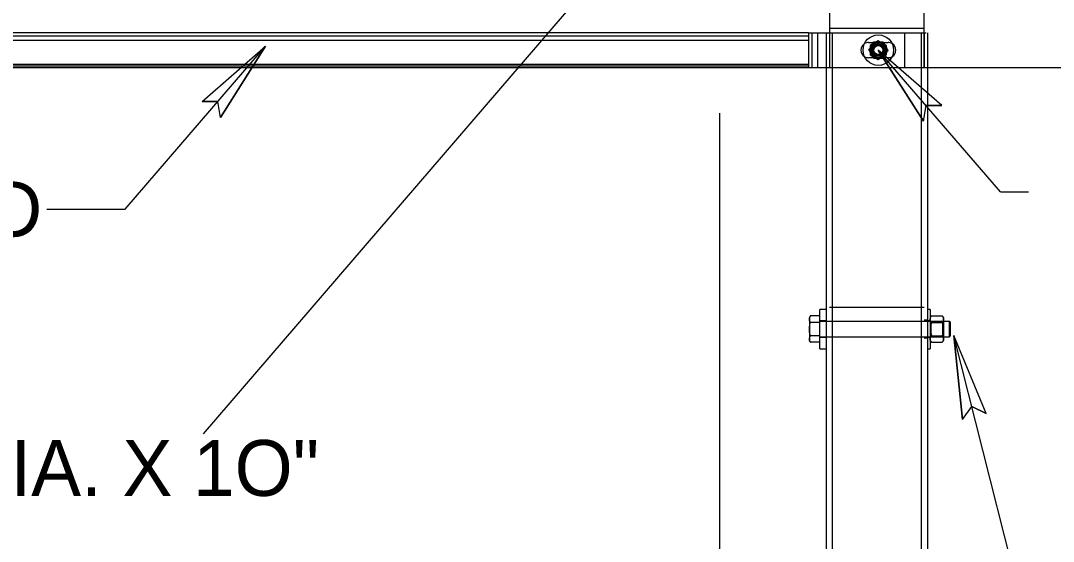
# Model space of a CAD drawing. Extents: x 12.2 to 54.5, y -7.8 to 16.1.
# Drawn here: x 14.18 to 15.289, y 14.128 to 14.687 of the extents above; entities that cross this region are included whole.
import ezdxf

# ---------------------------------------------------------------- set-up
doc = ezdxf.new("R2010")
doc.units = 0
for name, color, linetype in [('BORD-LINE', 7, 'Continuous'), ('DETL-DIMS', 7, 'Continuous'), ('DETL-NOTE', 7, 'Continuous')]:
    doc.layers.add(name, color=color, linetype=linetype)

msp = doc.modelspace()

# ---------------------------------------------------------------- linework, layer by layer
at = {"layer": 'BORD-LINE'}
for p, q in [((15.0489, 15.2577), (15.0489, 14.6363)), ((15.1503, 15.2577), (15.1503, 14.6362)), ((15.0264, 14.6743), (13.7714, 14.6743)), ((15.0264, 14.6706), (13.7714, 14.6706)), ((15.0264, 14.6743), (15.0264, 14.6369)), ((15.0264, 14.6743), (15.0358, 14.6743)), ((15.0299, 14.6743), (15.0299, 14.6369)), ((15.0358, 14.6743), (15.0358, 14.6369)), ((15.0358, 14.6743), (15.1294, 14.6743)), ((15.0451, 14.6743), (15.0451, 13.3257)), ((15.0517, 14.6743), (15.0517, 13.3257)), ((15.1294, 14.6743), (15.1294, 14.6369)), ((15.1294, 14.6743), (15.1528, 14.6743)), ((15.1474, 14.6743), (15.1474, 13.3257)), ((15.1505, 14.6743), (15.1505, 14.6369)), ((15.154, 14.6743), (15.154, 13.3257)), ((15.0264, 14.6659), (13.7714, 14.6659)), ((15.0908, 14.6638), (15.1119, 14.6638)), ((15.1013, 14.6657), (15.0926, 14.6606)), ((15.0926, 14.6606), (15.0926, 14.6506)), ((15.11, 14.6606), (15.1013, 14.6657)), ((15.11, 14.6506), (15.11, 14.6606)), ((15.1119, 14.6474), (15.0908, 14.6474)), ((15.0926, 14.6506), (15.1013, 14.6456)), ((15.1013, 14.6456), (15.11, 14.6506)), ((12.3965, 14.6369), (18.9405, 14.6369)), ((15.0264, 14.6403), (13.7714, 14.6403)), ((15.0264, 14.6384), (13.7714, 14.6384)), ((15.0487, 14.3794), (15.1507, 14.3794)), ((15.0272, 14.3682), (15.0272, 14.3666)), ((15.0386, 14.3701), (15.0283, 14.3701)), ((15.0386, 14.3348), (15.0386, 14.377)), ((15.1569, 14.377), (15.1569, 14.3348)), ((15.1586, 14.3701), (15.1698, 14.3701)), ((15.1715, 14.3682), (15.1715, 14.3666)), ((15.0272, 14.3666), (15.0272, 14.3559)), ((15.0386, 14.363), (15.0283, 14.363)), ((15.157, 14.3641), (15.157, 14.3559)), ((15.1577, 14.3631), (15.1577, 14.3487)), ((15.1586, 14.363), (15.1698, 14.363)), ((15.1707, 14.3559), (15.1707, 14.3631)), ((15.1715, 14.3666), (15.1715, 14.3559)), ((15.1778, 14.3477), (15.1778, 14.3641)), ((15.179, 14.349), (15.179, 14.3629)), ((15.0272, 14.3559), (15.0272, 14.3453)), ((15.0272, 14.3453), (15.0272, 14.3436)), ((15.0386, 14.3488), (15.0283, 14.3488)), ((15.157, 14.3559), (15.157, 14.3477)), ((15.1586, 14.3488), (15.1698, 14.3488)), ((15.1707, 14.3487), (15.1707, 14.3559)), ((15.1715, 14.3559), (15.1715, 14.3453)), ((15.1715, 14.3453), (15.1715, 14.3436)), ((15.0386, 14.3417), (15.0283, 14.3417)), ((15.1586, 14.3417), (15.1698, 14.3417))]:
    msp.add_line(p, q, dxfattribs=at)
for radius in [0.0164, 0.00819, 0.00702, 0.00614, 0.00585, 0.00498, 0.00484]:
    msp.add_circle((15.1013, 14.6556), radius, dxfattribs=at)
for centre, radius, start, end in [((15.0908, 14.6556), 0.00819, 121.5884, 238.4116), ((15.0908, 14.6556), 0.00819, 89.9961, 121.5935), ((15.1013, 14.6556), 0.00869, 119.9904, 180.0097), ((15.1013, 14.6556), 0.00878, 149.9916, 210.0084), ((15.1013, 14.6556), 0.00878, 89.9977, 150.0011), ((15.1013, 14.6556), 0.00869, 59.9984, 120.0016), ((15.1013, 14.6556), 0.00878, 29.9989, 89.9977), ((15.1013, 14.6556), 0.00869, 0.0053, 59.9946), ((15.1013, 14.6556), 0.00878, 329.9916, 30.0084), ((15.1119, 14.6556), 0.0082, 58.4163, 89.999), ((15.1119, 14.6556), 0.00819, 301.5884, 58.4116), ((15.0908, 14.6556), 0.00819, 238.409, 270.0014), ((15.1013, 14.6556), 0.00869, 179.9903, 240.0096), ((15.1013, 14.6556), 0.00878, 209.9989, 270.0023), ((15.1013, 14.6556), 0.00869, 239.9984, 300.0016), ((15.1013, 14.6556), 0.00878, 270.0023, 330.0011), ((15.1013, 14.6556), 0.00869, 300.0054, 359.9947), ((15.1119, 14.6556), 0.0082, 270.0057, 301.579)]:
    msp.add_arc(centre, radius, start, end, dxfattribs=at)
for points, degree in [([(15.0487, 14.679), (15.1504, 14.679)], 1), ([(15.0912, 14.6556), (15.0916, 14.6563), (15.0924, 14.6578), (15.0933, 14.6592), (15.0937, 14.66), (15.0937, 14.66)], 3), ([(15.0937, 14.66), (15.0941, 14.6606), (15.0948, 14.6618), (15.0956, 14.6633), (15.0961, 14.6642), (15.0963, 14.6644)], 3), ([(15.0963, 14.6644), (15.0967, 14.6644), (15.0977, 14.6644), (15.0994, 14.6644), (15.1007, 14.6644), (15.1013, 14.6644)], 3), ([(15.1013, 14.6644), (15.1015, 14.6644), (15.1022, 14.6644), (15.1036, 14.6644), (15.1052, 14.6644), (15.1061, 14.6644), (15.1064, 14.6644)], 3), ([(15.1064, 14.6644), (15.1068, 14.6637), (15.1076, 14.6623), (15.1085, 14.6608), (15.1089, 14.66), (15.1089, 14.66)], 3), ([(15.1089, 14.66), (15.1093, 14.6594), (15.11, 14.6582), (15.1109, 14.6567), (15.1113, 14.6559), (15.1115, 14.6556)], 3), ([(15.0937, 14.6512), (15.0934, 14.6518), (15.0927, 14.6531), (15.0918, 14.6545), (15.0913, 14.6554), (15.0912, 14.6556)], 3), ([(15.0963, 14.6468), (15.0959, 14.6475), (15.095, 14.649), (15.0942, 14.6504), (15.0937, 14.6512), (15.0937, 14.6512)], 3), ([(15.0963, 14.6468), (15.0967, 14.6468), (15.0977, 14.6468), (15.0994, 14.6468), (15.1007, 14.6468), (15.1013, 14.6468)], 3), ([(15.1013, 14.6468), (15.1015, 14.6468), (15.1022, 14.6468), (15.1036, 14.6468), (15.1052, 14.6468), (15.1061, 14.6468), (15.1064, 14.6468)], 3), ([(15.1089, 14.6512), (15.1086, 14.6506), (15.1079, 14.6494), (15.107, 14.6479), (15.1065, 14.6471), (15.1064, 14.6468)], 3), ([(15.1115, 14.6556), (15.1111, 14.6549), (15.1102, 14.6535), (15.1094, 14.652), (15.109, 14.6512), (15.1089, 14.6512)], 3), ([(15.0272, 14.3666), (15.0272, 14.3666), (15.0272, 14.3673), (15.0275, 14.3685), (15.0281, 14.3696), (15.0283, 14.3701)], 3), ([(15.0283, 14.3701), (15.0272, 14.3682)], 1), ([(15.045, 14.377), (15.0386, 14.377)], 1), ([(15.1569, 14.377), (15.1539, 14.377)], 1), ([(15.1569, 14.3666), (15.157, 14.3671), (15.1571, 14.3681), (15.1579, 14.3693), (15.1584, 14.3699), (15.1586, 14.3701)], 3), ([(15.1586, 14.3701), (15.1569, 14.3682)], 1), ([(15.1715, 14.3666), (15.1714, 14.3671), (15.1713, 14.3681), (15.1705, 14.3693), (15.17, 14.3699), (15.1698, 14.3701)], 3), ([(15.1715, 14.3682), (15.1698, 14.3701)], 1), ([(15.0283, 14.363), (15.028, 14.3636), (15.0274, 14.3647), (15.0273, 14.3659), (15.0272, 14.3666)], 3), ([(15.0272, 14.3559), (15.0273, 14.3569), (15.0273, 14.3587), (15.0278, 14.3611), (15.0282, 14.3625), (15.0283, 14.363)], 3), ([(15.0451, 14.3647), (15.0386, 14.3647)], 1), ([(15.1778, 14.3641), (15.0386, 14.3641)], 1), ([(15.1539, 14.3653), (15.1504, 14.3653)], 1), ([(15.1569, 14.3647), (15.1539, 14.3647)], 1), ([(15.1586, 14.363), (15.1581, 14.3635), (15.1573, 14.3646), (15.1569, 14.3659), (15.1569, 14.3665), (15.1569, 14.3666)], 3), ([(15.157, 14.3641), (15.1569, 14.3641)], 1), ([(15.1586, 14.363), (15.1583, 14.3624), (15.1578, 14.361), (15.1571, 14.3586), (15.157, 14.3568), (15.1569, 14.3559)], 3), ([(15.1577, 14.3631), (15.157, 14.3641)], 1), ([(15.1707, 14.3631), (15.1577, 14.3631)], 1), ([(15.1698, 14.363), (15.1703, 14.3635), (15.1711, 14.3646), (15.1715, 14.3659), (15.1715, 14.3665), (15.1715, 14.3666)], 3), ([(15.1698, 14.363), (15.1701, 14.3624), (15.1706, 14.361), (15.1713, 14.3586), (15.1714, 14.3568), (15.1715, 14.3559)], 3), ([(15.1715, 14.3641), (15.1707, 14.3631)], 1), ([(15.179, 14.3629), (15.1778, 14.3641)], 1), ([(15.0283, 14.3488), (15.0281, 14.3497), (15.0276, 14.3515), (15.0273, 14.3539), (15.0273, 14.3554), (15.0272, 14.3559)], 3), ([(15.0272, 14.3453), (15.0272, 14.3454), (15.0272, 14.346), (15.0275, 14.3473), (15.0281, 14.3483), (15.0283, 14.3488)], 3), ([(15.0283, 14.3417), (15.028, 14.3423), (15.0274, 14.3434), (15.0273, 14.3447), (15.0272, 14.3453)], 3), ([(15.0386, 14.3477), (15.1778, 14.3477)], 1), ([(15.0386, 14.3471), (15.045, 14.3471)], 1), ([(15.1504, 14.3466), (15.1539, 14.3466)], 1), ([(15.1539, 14.3471), (15.1569, 14.3471)], 1), ([(15.1569, 14.3559), (15.1569, 14.3558), (15.1569, 14.3547), (15.1572, 14.3527), (15.1579, 14.3505), (15.1584, 14.3492), (15.1586, 14.3488)], 3), ([(15.1569, 14.3453), (15.157, 14.3458), (15.1571, 14.3469), (15.1579, 14.348), (15.1584, 14.3486), (15.1586, 14.3488)], 3), ([(15.1569, 14.3477), (15.157, 14.3477)], 1), ([(15.1586, 14.3417), (15.1581, 14.3423), (15.1573, 14.3433), (15.1569, 14.3446), (15.1569, 14.3453), (15.1569, 14.3453)], 3), ([(15.1569, 14.3453), (15.157, 14.3451)], 1), ([(15.157, 14.3477), (15.1577, 14.3487)], 1), ([(15.1577, 14.3487), (15.1707, 14.3487)], 1), ([(15.1715, 14.3559), (15.1715, 14.3558), (15.1715, 14.3547), (15.1712, 14.3527), (15.1705, 14.3505), (15.17, 14.3492), (15.1698, 14.3488)], 3), ([(15.1715, 14.3453), (15.1714, 14.3458), (15.1713, 14.3469), (15.1705, 14.348), (15.17, 14.3486), (15.1698, 14.3488)], 3), ([(15.1698, 14.3417), (15.1703, 14.3423), (15.1711, 14.3433), (15.1715, 14.3446), (15.1715, 14.3453), (15.1715, 14.3453)], 3), ([(15.1707, 14.3487), (15.1715, 14.3477)], 1), ([(15.1778, 14.3477), (15.179, 14.349)], 1), ([(15.0272, 14.3436), (15.0283, 14.3417)], 1), ([(15.0386, 14.3348), (15.045, 14.3348)], 1), ([(15.1539, 14.3348), (15.1569, 14.3348)], 1), ([(15.1569, 14.3436), (15.1586, 14.3417)], 1), ([(15.1698, 14.3417), (15.1715, 14.3436)], 1)]:
    msp.add_open_spline(points, degree=degree, dxfattribs=at)
at = {"layer": 'DETL-DIMS'}
for p, q in [((14.3764, 14.2433), (15.1013, 15.0864)), ((14.292, 14.4846), (14.443, 14.6598)), ((14.3748, 14.6004), (14.443, 14.6598)), ((14.3945, 14.5833), (14.443, 14.6598)), ((15.2326, 14.5033), (15.1013, 14.6556)), ((15.1499, 14.5791), (15.1013, 14.6556)), ((15.1696, 14.5962), (15.1013, 14.6556)), ((14.3748, 14.6004), (14.3918, 14.6004)), ((14.3945, 14.5833), (14.3918, 14.6004)), ((15.1499, 14.5791), (15.1526, 14.5962)), ((15.1696, 14.5962), (15.1526, 14.5962)), ((14.931, 13.8194), (14.931, 14.5877)), ((15.2326, 14.5033), (15.2626, 14.5033)), ((14.208, 14.4846), (14.292, 14.4846)), ((15.2859, 13.9398), (15.1826, 14.349)), ((15.1918, 14.2589), (15.1826, 14.349)), ((15.2171, 14.2652), (15.1826, 14.349)), ((15.1918, 14.2589), (15.2018, 14.2728)), ((15.2171, 14.2652), (15.2018, 14.2728))]:
    msp.add_line(p, q, dxfattribs=at)
for points in [[(14.3748, 14.6004), (14.443, 14.6598), (14.3945, 14.5833), (14.3918, 14.6004)], [(15.1696, 14.5962), (15.1013, 14.6556), (15.1499, 14.5791), (15.1526, 14.5962)], [(15.2171, 14.2652), (15.1826, 14.349), (15.1918, 14.2589), (15.2018, 14.2728)]]:
    msp.add_lwpolyline(points, close=True, dxfattribs=at)

# ---------------------------------------------------------------- texts
at = {"layer": 'DETL-NOTE'}
for s, p in [('GROUND', (13.8465, 14.4546)), ('5/8" DIA. X 1O"', (13.9487, 14.1767))]:
    msp.add_text(s, height=0.06, dxfattribs=at).set_placement(p)

doc.saveas('drawing.dxf')
